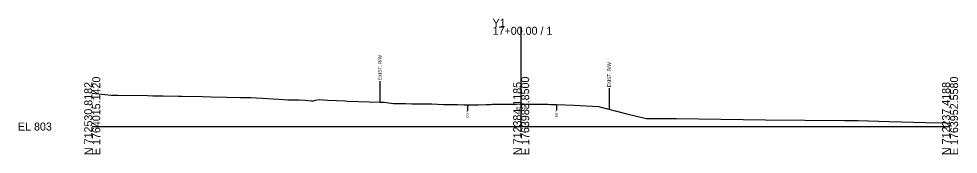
# Model space of a CAD drawing. Extents: x -26 to 1303, y -10 to 9524.
# Drawn here: x -25.7 to 302.8, y 6990.3 to 7037.7 of the extents above; entities that cross this region are included whole.
import ezdxf

# ---------------------------------------------------------------- set-up
doc = ezdxf.new("R2010")
doc.units = 0
for name, color, linetype in [('Default', 7, 'Continuous'), ('Exist Cross Section Cell', 7, 'Continuous'), ('Exist XS Center Line Elevation Label', 7, 'Continuous'), ('Exist XS Ground Line', 7, 'Continuous'), ('Old_Level_10', 7, 'Continuous')]:
    doc.layers.add(name, color=color, linetype=linetype)

msp = doc.modelspace()

# ---------------------------------------------------------------- linework, layer by layer
at = {"layer": 'Exist Cross Section Cell'}
for p, q in [((150, 7000), (150, 7034.92)), ((0, 7000), (150, 7000)), ((150, 7000), (300, 7000))]:
    msp.add_line(p, q, dxfattribs=at)
at = {"layer": 'Exist XS Ground Line'}
msp.add_lwpolyline([(0, 7011.64), (6.58, 7010.97), (8.81, 7010.95), (19.29, 7010.81), (21.21, 7010.77), (24.72, 7010.73), (30.19, 7010.65), (31.35, 7010.64), (38.61, 7010.47), (41.58, 7010.43), (47.04, 7010.29), (51.8, 7010.2), (55.47, 7010.11), (65.28, 7009.55), (68.41, 7009.4), (72, 7009.32), (72.4, 7009.31), (74.51, 7009.18), (76.65, 7009.04), (77.37, 7009.02), (78.09, 7009.2), (79.36, 7009.48), (82.41, 7009.25), (88.5, 7008.96), (89.3, 7008.93), (100.67, 7008.54), (102.09, 7008.49), (105.36, 7008.06), (109.56, 7008.02), (111.74, 7007.94), (113.85, 7007.92), (118.73, 7007.9), (122.73, 7007.71), (126.79, 7007.67), (127.72, 7007.66), (130.05, 7007.62), (130.5, 7007.65), (131.19, 7007.59), (132.71, 7007.58), (134.1, 7007.58), (135.04, 7007.57), (137.6, 7007.67), (137.92, 7007.69), (139.38, 7007.76), (140, 7007.78), (141.97, 7007.79), (142.71, 7007.8), (144.07, 7007.82), (145.26, 7007.86), (146.18, 7007.86), (147.82, 7007.88), (148.42, 7007.89), (149.7, 7007.91), (150.2, 7007.91), (150.8, 7007.92), (152.93, 7007.89), (153.6, 7007.89), (155.49, 7007.88), (156.85, 7007.84), (158.05, 7007.8), (158.82, 7007.79), (159.27, 7007.79), (160.25, 7007.77), (160.56, 7007.77), (160.86, 7007.76), (161.19, 7007.75), (162.01, 7007.73), (162.38, 7007.71), (168.49, 7007.45), (177.06, 7007.06), (186.91, 7004.42), (193.74, 7002.82), (200.76, 7002.8), (204.34, 7002.77), (227.65, 7002.46), (235.42, 7002.36), (263.13, 7002.12), (264.04, 7002.11), (267.83, 7002.08), (275.03, 7001.9), (278.71, 7001.76), (291.48, 7001.43), (298.46, 7001.28), (300, 7001.2)], dxfattribs=at)
at = {"layer": 'Old_Level_10'}
for p, q in [((100.6, 7015.94), (100.6, 7008.54)), ((180.78, 7013.46), (180.78, 7006.06)), ((162.38, 7007.71), (162.38, 7005.66)), ((131.19, 7007.59), (131.19, 7005.54))]:
    msp.add_line(p, q, dxfattribs=at)

# ---------------------------------------------------------------- texts
at = {"layer": 'Default'}
msp.add_text('-', height=0.0001, dxfattribs=at).set_placement((0, 7000))
at = {"layer": 'Exist Cross Section Cell'}
for s, p in [('Y1', (140, 7034.92)), ('17+00.00 / 1', (140, 7032.12)), ('EL 803', (-26, 6998.6))]:
    msp.add_text(s, height=2.8, dxfattribs=at).set_placement(p)
for s, p in [('N 712530.8182', (0, 6990)), ('E 1764015.1420', (2.8, 6990)), ('N 712384.1185', (150, 6990)), ('E 1763983.8500', (152.8, 6990)), ('N 712237.4188', (300, 6990)), ('E 1763952.5580', (302.8, 6990))]:
    msp.add_text(s, height=2.8, rotation=90, dxfattribs=at).set_placement(p)
at = {"layer": 'Exist XS Center Line Elevation Label'}
msp.add_text('810.91', height=1, dxfattribs=at).set_placement((148.16, 7005.91))
at = {"layer": 'Old_Level_10'}
for s, height, p in [('EXIST. R/W', 1.181, (101.19, 7016.24)), ('EXIST. R/W', 1.181, (181.37, 7013.76)), ('EOP', 0.787, (131.58, 7003.15)), ('EOP', 0.787, (162.77, 7003.26))]:
    msp.add_text(s, height=height, rotation=90, dxfattribs=at).set_placement(p)

doc.saveas('drawing.dxf')
